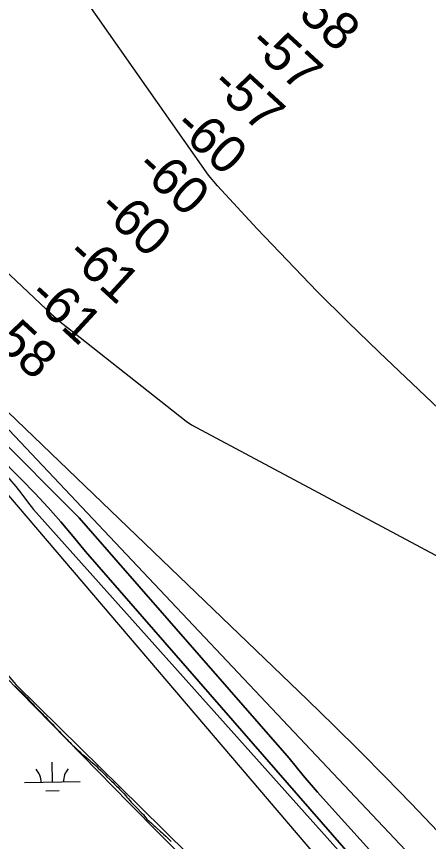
# Model space of a CAD drawing. Extents: x 3903937 to 3942190, y 260677 to 286651.
# Drawn here: x 3924835 to 3925573, y 275569 to 277048 of the extents above; entities that cross this region are included whole.
import ezdxf

# ---------------------------------------------------------------- set-up
doc = ezdxf.new("R2010")
doc.units = 0
for name, color, linetype in [('V-RIVR-EDGE', 7, 'Continuous'), ('V-RIVR-RANG', 7, 'Continuous'), ('V-RRAP-FSHR', 7, 'Continuous'), ('V-TOPO-DPTH', 7, 'Continuous'), ('V-TOPO-MAJR', 7, 'Continuous'), ('V-TOPO-MINR', 7, 'Continuous'), ('V-WETL-SWMP', 7, 'Continuous')]:
    doc.layers.add(name, color=color, linetype=linetype)

msp = doc.modelspace()

# ---------------------------------------------------------------- linework, layer by layer
at = {"layer": 'V-RIVR-EDGE'}
msp.add_lwpolyline([(3923809, 277077.5), (3923935, 276930.6), (3924022.1, 276825.6), (3924100.8, 276727), (3924229.9, 276553.8), (3924320.2, 276432.1), (3924352.7, 276398.5), (3924369.5, 276368), (3924377.9, 276353.3), (3924399.9, 276333.4), (3924463.9, 276262), (3924585.7, 276132.9), (3924651.8, 276050), (3924729.5, 275971.3), (3924833.4, 275850.6), (3924912.1, 275772.9), (3925056.9, 275630.2), (3925314.1, 275376.2)], dxfattribs=at)
at = {"layer": 'V-RRAP-FSHR'}
msp.add_lwpolyline([(3925149.5, 275524.3), (3925092.7, 275580.7), (3925036.7, 275637.8), (3924980.7, 275694.9), (3924924.6, 275752.4), (3924868.6, 275809.2), (3924812.6, 275866.3)], dxfattribs=at)
at = {"layer": 'V-TOPO-DPTH'}
for points in [[(3925522.9, 275492.5), (3925400.1, 275628), (3925373.9, 275657.5), (3925348.2, 275687.5), (3925323.2, 275718), (3924947.3, 276149.2), (3924790.6, 276305.6), (3924772.5, 276323.6), (3924754.4, 276341.6), (3924736.2, 276359.5), (3924718, 276377.3), (3924461.7, 276628.1), (3924366, 276721.5), (3924270.2, 276814.7), (3924174.2, 276907.8), (3924078, 277000.7), (3923910.7, 277162.1)], [(3925522.9, 275492.5), (3925400.1, 275628), (3925373.9, 275657.5), (3925348.2, 275687.5), (3925323.2, 275718), (3924947.3, 276149.2), (3924790.6, 276305.6), (3924772.5, 276323.6), (3924754.4, 276341.6), (3924736.2, 276359.5), (3924718, 276377.3), (3924461.7, 276628.1), (3924366, 276721.5), (3924270.2, 276814.7), (3924174.2, 276907.8), (3924078, 277000.7), (3923910.7, 277162.1)], [(3923937.3, 277163), (3924349.5, 276765), (3924419.6, 276697.3), (3924489.7, 276629.5), (3924559.7, 276561.7), (3924629.7, 276493.8), (3924717, 276409), (3924743.2, 276383.5), (3924769.4, 276357.9), (3924795.5, 276332.2), (3924821.6, 276306.4), (3925552, 275532.1)], [(3925552, 275532.1), (3924821.6, 276306.4), (3924795.5, 276332.2), (3924769.4, 276357.9), (3924743.2, 276383.5), (3924717, 276409), (3924629.7, 276493.8), (3924559.7, 276561.7), (3924489.7, 276629.5), (3924419.6, 276697.3), (3924349.5, 276765), (3923937.3, 277163)], [(3923865.2, 277116.3), (3923945.8, 277041.5), (3924026.2, 276966.7), (3924106.5, 276891.6), (3924186.7, 276816.5), (3924428.2, 276589.5), (3924477.6, 276542.8), (3924526.8, 276495.8), (3924575.6, 276448.5), (3924624.2, 276400.9), (3924719.8, 276306.6), (3924721, 276305.4), (3924721.6, 276304.8), (3924722.3, 276304.2), (3924727.9, 276298.5), (3924730.5, 276295.7), (3924731.7, 276294.3), (3924734.1, 276291.2), (3924736.1, 276288), (3924737, 276286.3), (3925453.2, 275446.6)], [(3925522.6, 275441.3), (3924958.2, 276088.7), (3924936.5, 276115.6), (3924914.1, 276141.9), (3924891.3, 276167.9), (3924867.7, 276193.2), (3924843.7, 276218), (3924757.4, 276304.8), (3924747.8, 276314.5), (3924738.2, 276324), (3924728.6, 276333.6), (3924718.9, 276343.2), (3924144.8, 276908.9), (3924099.8, 276953.1), (3924054.7, 276997.2), (3924009.4, 277041.2), (3923964.1, 277085.1)], [(3923964.1, 277085.1), (3924009.4, 277041.2), (3924054.7, 276997.2), (3924099.8, 276953.1), (3924144.8, 276908.9), (3924718.9, 276343.2), (3924728.6, 276333.6), (3924738.2, 276324), (3924747.8, 276314.5), (3924757.4, 276304.8), (3924843.7, 276218), (3924867.7, 276193.2), (3924891.3, 276167.9), (3924914.1, 276141.9), (3924936.5, 276115.6), (3924958.2, 276088.7), (3925522.6, 275441.3)]]:
    msp.add_lwpolyline(points, dxfattribs=at)
at = {"layer": 'V-TOPO-MAJR'}
msp.add_lwpolyline([(3923970, 277163.9), (3924677.9, 276475), (3924695.4, 276457.9), (3924713, 276440.9), (3924730.6, 276423.9), (3924748.2, 276406.9), (3924778.8, 276377.4), (3924781.1, 276375.2), (3924783.4, 276373), (3924785.7, 276370.8), (3924788, 276368.6), (3925356.2, 275822.7), (3925403.2, 275777), (3925449.9, 275730.8), (3925496, 275684), (3925541.6, 275636.9), (3925589.3, 275587), (3925610.7, 275564.3)], dxfattribs=at)
at = {"layer": 'V-TOPO-MINR'}
for points in [[(3925994.8, 275960.8), (3925484.5, 276446.1), (3925428.6, 276500.2), (3925373.5, 276555), (3925319.4, 276610.9), (3925266, 276667.4), (3925194.7, 276744.4), (3925178.6, 276763.6), (3924483.8, 277753.9)], [(3924059.5, 277310.9), (3924398.3, 276987.2), (3924482.7, 276906.7), (3924567.2, 276826.4), (3924651.8, 276746.2), (3924736.5, 276666.1), (3924887.7, 276523.4), (3924897, 276514.8), (3924906.5, 276506.4), (3924916.2, 276498.3), (3924926, 276490.3), (3925138.6, 276322.2), (3925148.3, 276315.8), (3925977.9, 275872.5)], [(3923910.7, 277162.1), (3924078, 277000.7), (3924174.2, 276907.8), (3924270.2, 276814.7), (3924366, 276721.5), (3924461.7, 276628.1), (3924718, 276377.3), (3924736.2, 276359.5), (3924754.4, 276341.6), (3924772.5, 276323.6), (3924790.6, 276305.6), (3924947.3, 276149.2), (3925323.2, 275718), (3925348.2, 275687.5), (3925373.9, 275657.5), (3925400.1, 275628), (3925522.9, 275492.5)], [(3923937.3, 277163), (3924349.5, 276765), (3924419.6, 276697.3), (3924489.7, 276629.5), (3924559.7, 276561.7), (3924629.7, 276493.8), (3924717, 276409), (3924743.2, 276383.5), (3924769.4, 276357.9), (3924795.5, 276332.2), (3924821.6, 276306.4), (3925552, 275532.1)], [(3923865.2, 277116.3), (3923945.8, 277041.5), (3924026.2, 276966.7), (3924106.5, 276891.6), (3924186.7, 276816.5), (3924428.2, 276589.5), (3924477.6, 276542.8), (3924526.8, 276495.8), (3924575.6, 276448.5), (3924624.2, 276400.9), (3924719.8, 276306.6), (3924721, 276305.4), (3924721.6, 276304.8), (3924722.3, 276304.2), (3924727.9, 276298.5), (3924730.5, 276295.7), (3924731.7, 276294.3), (3924734.1, 276291.2), (3924736.1, 276288), (3924737, 276286.3), (3925453.2, 275446.6)], [(3923964.1, 277085.1), (3924009.4, 277041.2), (3924054.7, 276997.2), (3924099.8, 276953.1), (3924144.8, 276908.9), (3924718.9, 276343.2), (3924728.6, 276333.6), (3924738.2, 276324), (3924747.8, 276314.5), (3924757.4, 276304.8), (3924843.7, 276218), (3924867.7, 276193.2), (3924891.3, 276167.9), (3924914.1, 276141.9), (3924936.5, 276115.6), (3924958.2, 276088.7), (3925522.6, 275441.3)], [(3923968.5, 277067.6), (3923988.6, 277047.8), (3924719.4, 276325.2), (3924724.6, 276320), (3924729.8, 276314.9), (3924734.9, 276309.7), (3924740.1, 276304.5), (3924787.1, 276257.1), (3924799.1, 276244.5), (3924810.9, 276231.8), (3924822.3, 276218.7), (3924833.4, 276205.4), (3924844.2, 276191.8), (3924854.7, 276178), (3924865, 276164), (3925522.6, 275428.4)]]:
    msp.add_lwpolyline(points, dxfattribs=at)
at = {"layer": 'V-WETL-SWMP'}
for p, q in [((3924832, 275847.9), (3924835.2, 275844.4)), ((3924835.2, 275844.4), (3924837.7, 275841.9)), ((3924837.7, 275841.9), (3924840.4, 275839.4)), ((3924840.4, 275839.4), (3924843.2, 275836.9)), ((3924843.2, 275836.9), (3924847.2, 275833.3)), ((3924847.2, 275833.3), (3924851, 275829.6)), ((3924851, 275829.6), (3924853.5, 275826.9)), ((3924853.5, 275826.9), (3924857.6, 275822.5)), ((3924857.6, 275822.5), (3924860.3, 275819.4)), ((3924860.3, 275819.4), (3924864.3, 275815.4)), ((3924864.3, 275815.4), (3924866.7, 275812.8)), ((3924866.7, 275812.8), (3924870.1, 275809.3)), ((3924870.1, 275809.3), (3924872.2, 275806.9)), ((3924872.2, 275806.9), (3924875.3, 275803.5)), ((3924875.3, 275803.5), (3924877.6, 275801.1)), ((3924877.6, 275801.1), (3924881.2, 275797.6)), ((3924881.2, 275797.6), (3924883.8, 275795)), ((3924883.8, 275795), (3924886.5, 275792.3)), ((3924886.5, 275792.3), (3924890.3, 275788.3)), ((3924890.3, 275788.3), (3924892.9, 275785.8)), ((3924892.9, 275785.8), (3924896.8, 275781.7)), ((3924896.8, 275781.7), (3924899.4, 275779.1)), ((3924899.4, 275779.1), (3924903.1, 275775.3)), ((3924903.1, 275775.3), (3924906.6, 275771.5)), ((3924906.6, 275771.5), (3924908.8, 275769)), ((3924908.8, 275769), (3924912.1, 275765.4)), ((3924912.1, 275765.4), (3924914.3, 275763.2)), ((3924914.3, 275763.2), (3924917.7, 275759.4)), ((3924917.7, 275759.4), (3924919.9, 275757.1)), ((3924919.9, 275757.1), (3924925.4, 275751.7)), ((3924925.4, 275751.7), (3924927.6, 275749.4)), ((3924927.6, 275749.4), (3924930.7, 275746.3)), ((3924930.7, 275746.3), (3924932.9, 275744.2)), ((3924932.9, 275744.2), (3924935.8, 275741.2)), ((3924935.8, 275741.2), (3924938.1, 275739)), ((3924938.1, 275739), (3924943.3, 275734.1)), ((3924943.3, 275734.1), (3924948.1, 275729.6)), ((3924948.1, 275729.6), (3924950.9, 275726.9)), ((3924950.9, 275726.9), (3924955.8, 275722.8)), ((3924955.8, 275722.8), (3924960.7, 275718.8)), ((3924960.7, 275718.8), (3924964.8, 275715.1)), ((3924899.1, 275675.4), (3924898.4, 275711.4)), ((3924964.8, 275715.1), (3924968, 275712.3)), ((3924968, 275712.3), (3924973, 275708.2)), ((3924973, 275708.2), (3924977.2, 275704.3)), ((3924977.2, 275704.3), (3924981.2, 275700.4)), ((3924981.2, 275700.4), (3924985.6, 275696)), ((3924985.6, 275696), (3924990.4, 275691.3)), ((3924990.4, 275691.3), (3924993.3, 275688.5)), ((3924993.3, 275688.5), (3924996.8, 275685.1)), ((3924849.1, 275674.5), (3924949, 275676.3)), ((3924996.8, 275685.1), (3925001.7, 275680.3)), ((3925001.7, 275680.3), (3925004.9, 275677.1)), ((3925004.9, 275677.1), (3925007.2, 275675)), ((3925007.2, 275675), (3925010.6, 275671.5)), ((3924887.3, 275659.8), (3924911.3, 275660.2)), ((3925010.6, 275671.5), (3925013.9, 275668.1)), ((3925013.9, 275668.1), (3925016.2, 275666.1)), ((3925016.2, 275666.1), (3925019.5, 275662.8)), ((3925019.5, 275662.8), (3925021.6, 275660.6)), ((3925021.6, 275660.6), (3925024.7, 275657.2)), ((3925024.7, 275657.2), (3925027.1, 275654.7)), ((3925027.1, 275654.7), (3925030.4, 275651)), ((3925030.4, 275651), (3925032.5, 275648.4)), ((3925032.5, 275648.4), (3925034.8, 275645.9)), ((3925034.8, 275645.9), (3925037.9, 275642.2)), ((3925037.9, 275642.2), (3925040.3, 275639.6)), ((3925040.3, 275639.6), (3925043.6, 275635.8)), ((3925043.6, 275635.8), (3925046, 275633.3)), ((3925046, 275633.3), (3925049.5, 275629.6)), ((3925049.5, 275629.6), (3925052, 275627.2)), ((3925052, 275627.2), (3925057, 275622)), ((3925057, 275622), (3925059.5, 275619.7)), ((3925059.5, 275619.7), (3925062, 275617)), ((3925062, 275617), (3925064.1, 275614.3)), ((3925064.1, 275614.3), (3925066.2, 275611.6)), ((3925066.2, 275611.6), (3925068.5, 275609)), ((3925068.5, 275609), (3925072.6, 275605.1)), ((3925072.6, 275605.1), (3925076.6, 275601.5)), ((3925076.6, 275601.5), (3925080.6, 275597.8)), ((3925080.6, 275597.8), (3925083.1, 275595.6)), ((3925083.1, 275595.6), (3925086.9, 275592.2)), ((3925086.9, 275592.2), (3925092.1, 275587.6)), ((3925092.1, 275587.6), (3925095.7, 275584.2)), ((3925095.7, 275584.2), (3925098, 275581.9)), ((3925098, 275581.9), (3925102, 275578.2)), ((3925102, 275578.2), (3925104.4, 275575.9)), ((3925104.4, 275575.9), (3925108.2, 275572.2)), ((3925108.2, 275572.2), (3925111.7, 275568.9))]:
    msp.add_line(p, q, dxfattribs=at)
for centre, start, end in [((3924843.8, 275674.9), 0.2366, 41.7802), ((3924954.3, 275676.8), 140.2366, 181.7802)]:
    msp.add_arc(centre, 35.2, start, end, dxfattribs=at)

# ---------------------------------------------------------------- texts
at = {"layer": 'V-RIVR-RANG'}
for s, p in [('-58', (3925315.8, 277069.1)), ('-57', (3925248.1, 276995.5)), ('-57', (3925180.3, 276922)), ('-60', (3925113.7, 276847.4)), ('-60', (3925045.8, 276773.9)), ('-60', (3924978, 276700.4)), ('-61', (3924921.1, 276617)), ('-61', (3924853.3, 276543.5)), ('-58', (3924773.2, 276481.2))]:
    msp.add_text(s, height=67, rotation=317.4391, dxfattribs=at).set_placement(p)

doc.saveas('drawing.dxf')
